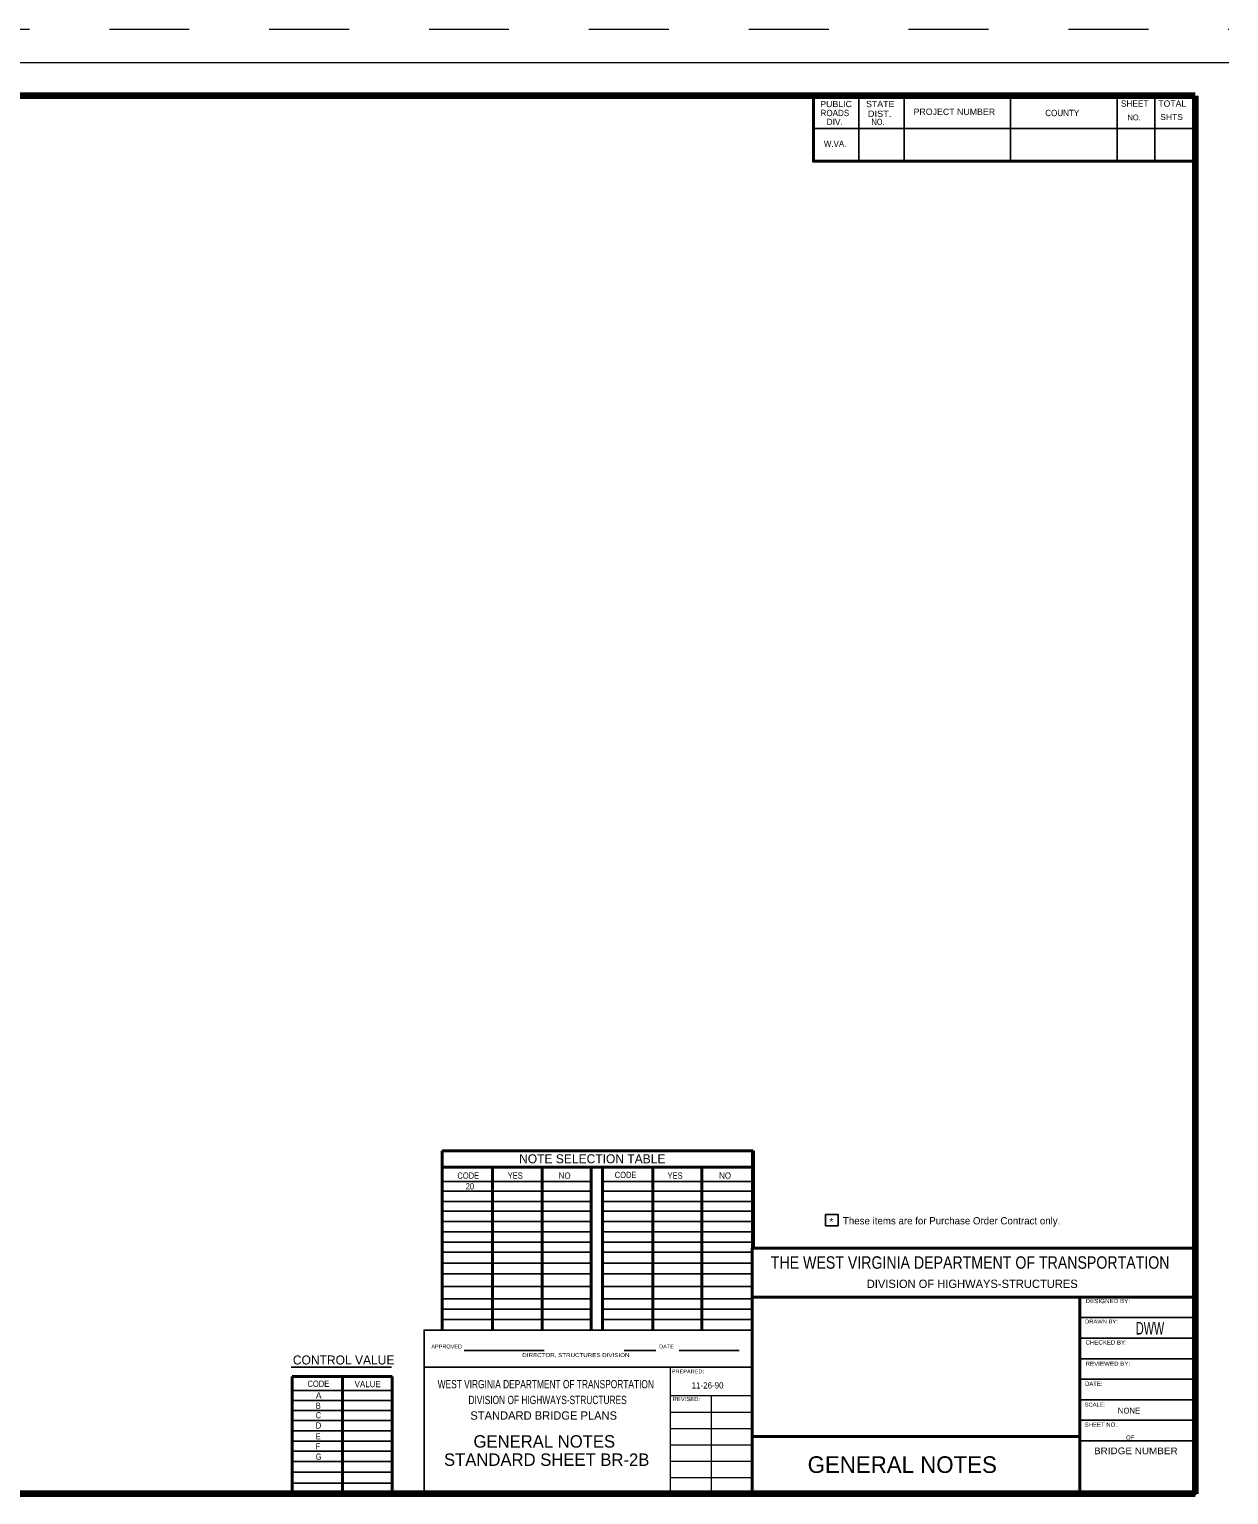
# Model space of a CAD drawing. Extents: x -2.94 to 3.45, y 0.57 to 4.
# Drawn here: x -1.435 to 0.065, y 2.169 to 4.003 of the extents above; entities that cross this region are included whole.
import ezdxf
from ezdxf.enums import TextEntityAlignment as Align

# ---------------------------------------------------------------- set-up
doc = ezdxf.new("R2010")
doc.units = 0
doc.header["$LTSCALE"] = 0.0036
doc.header["$PDMODE"] = 32
doc.header["$PDSIZE"] = 0.0018
doc.linetypes.add('DOTTED', pattern=[1.5, 0.3, -1.2])
doc.linetypes.add('LONG_DASHED', pattern=[7.5, 6, -1.5])
for name, color, linetype, lineweight in [('1', 7, 'Continuous', 13), ('3', 7, 'Continuous', 25), ('61', 7, 'Continuous', 25)]:
    doc.layers.add(name, color=color, linetype=linetype, lineweight=lineweight)

msp = doc.modelspace()

# ---------------------------------------------------------------- linework, layer by layer
at = {"layer": '1', "linetype": 'LONG_DASHED'}
msp.add_line((-2.935167, 4.002917), (0.065333, 4.002917), dxfattribs=at)
at = {"layer": '1'}
for p, q in [((-2.935167, 3.96125), (0.065333, 3.96125)), ((-0.633417, 2.328333), (-0.633417, 2.169667)), ((-0.633417, 2.292833), (-0.530833, 2.292833)), ((-0.582167, 2.29325), (-0.582167, 2.169667)), ((-0.633417, 2.27225), (-0.530833, 2.27225)), ((-0.633417, 2.251667), (-0.530833, 2.251667)), ((-0.633417, 2.231167), (-0.530833, 2.231167)), ((-0.633417, 2.21075), (-0.530833, 2.21075)), ((-0.633417, 2.190167), (-0.530833, 2.190167))]:
    msp.add_line(p, q, dxfattribs=at)
at = {"layer": '1', "lineweight": 158}
for p, q in [((0.023417, 3.919667), (-2.789083, 3.919667)), ((0.023417, 3.919667), (0.023417, 2.169667)), ((0.023417, 2.169667), (-2.789083, 2.169667))]:
    msp.add_line(p, q, dxfattribs=at)
at = {"layer": '1', "lineweight": 25}
for p, q in [((-0.3975, 3.919667), (-0.3975, 3.837667)), ((-0.340917, 3.919667), (-0.340917, 3.837667)), ((-0.2075, 3.919667), (-0.2075, 3.837667)), ((-0.07425, 3.919667), (-0.07425, 3.837667)), ((-0.026917, 3.919667), (-0.026917, 3.837667)), ((-0.454167, 3.87875), (0.023417, 3.87875)), ((-0.12075, 2.390417), (0.023417, 2.390417)), ((-0.9415, 2.37475), (-0.530833, 2.37475)), ((-0.9415, 2.37475), (-0.530833, 2.37475)), ((-0.12075, 2.3645), (0.023417, 2.3645)), ((-0.12075, 2.338667), (0.023417, 2.338667)), ((-0.9415, 2.328333), (-0.530833, 2.328333)), ((-0.12075, 2.313167), (0.023417, 2.313167)), ((-0.12075, 2.287417), (0.023417, 2.287417)), ((-0.12075, 2.262), (0.023417, 2.262)), ((-0.12075, 2.236), (0.023417, 2.236))]:
    msp.add_line(p, q, dxfattribs=at)
at = {"layer": '1', "lineweight": 40}
for p, q in [((-0.530833, 2.415833), (0.023417, 2.415833)), ((-0.12075, 2.415833), (-0.12075, 2.169667)), ((-0.530833, 2.241417), (-0.12075, 2.241417))]:
    msp.add_line(p, q, dxfattribs=at)
at = {"layer": '1', "linetype": 'DOTTED', "lineweight": 25}
for p, q in [((-0.89125, 2.349083), (-0.651583, 2.349083)), ((-0.622417, 2.349083), (-0.547083, 2.349083))]:
    msp.add_line(p, q, dxfattribs=at)
at = {"layer": '1', "lineweight": 40}
for points in [[(-0.454167, 3.919667), (-0.454167, 3.837667), (0.023417, 3.837667)], [(-0.530833, 2.169667), (-0.530833, 2.477333), (0.023417, 2.477333)]]:
    msp.add_lwpolyline(points, dxfattribs=at)
at = {"layer": '1', "lineweight": 25}
msp.add_lwpolyline([(-0.9415, 2.169667), (-0.9415, 2.37475), (-0.530833, 2.37475)], dxfattribs=at)
at = {"layer": '1'}
msp.add_point((0.023417, 2.169667), dxfattribs=at)
at = {"layer": '3'}
msp.add_lwpolyline([(-0.439083, 2.519583), (-0.439083, 2.505333), (-0.4235, 2.505333), (-0.4235, 2.519583)], close=True, dxfattribs=at)
at = {"layer": '61', "lineweight": 40}
for p, q in [((-0.918833, 2.599), (-0.918833, 2.37475)), ((-0.918833, 2.599), (-0.52975, 2.599)), ((-0.918917, 2.578583), (-0.529833, 2.578583)), ((-0.856, 2.37475), (-0.856, 2.578417)), ((-0.793833, 2.37475), (-0.793833, 2.578583)), ((-0.7325, 2.37475), (-0.7325, 2.578667)), ((-0.718, 2.37475), (-0.718, 2.5785)), ((-0.65525, 2.37475), (-0.65525, 2.5785)), ((-0.593833, 2.37475), (-0.593833, 2.578583)), ((-0.918833, 2.5245), (-0.918833, 2.511333)), ((-1.1065, 2.31675), (-0.981417, 2.31675)), ((-1.106417, 2.316833), (-1.106417, 2.17025)), ((-1.043583, 2.170167), (-1.043583, 2.3165)), ((-0.981417, 2.17025), (-0.981417, 2.31675)), ((-1.106417, 2.262583), (-1.106417, 2.2495)), ((-1.106417, 2.170167), (-0.981417, 2.170167))]:
    msp.add_line(p, q, dxfattribs=at)
at = {"layer": '61', "lineweight": 53}
msp.add_line((-0.529833, 2.477333), (-0.529833, 2.599), dxfattribs=at)
at = {"layer": '61'}
for p, q in [((-0.7325, 2.560917), (-0.919, 2.560917)), ((-0.529833, 2.560917), (-0.718083, 2.560917)), ((-0.7325, 2.5485), (-0.918917, 2.5485)), ((-0.732417, 2.535917), (-0.918833, 2.535917)), ((-0.529833, 2.5485), (-0.718083, 2.5485)), ((-0.529833, 2.535917), (-0.718083, 2.535917)), ((-0.732417, 2.5235), (-0.918833, 2.5235)), ((-0.918833, 2.522833), (-0.918833, 2.50725)), ((-0.529833, 2.5235), (-0.718083, 2.5235)), ((-0.918917, 2.5105), (-0.732417, 2.5105)), ((-0.918917, 2.49775), (-0.7325, 2.49775)), ((-0.918833, 2.498167), (-0.918833, 2.485)), ((-0.718083, 2.5105), (-0.530833, 2.5105)), ((-0.718083, 2.49775), (-0.530833, 2.49775)), ((-0.918833, 2.485417), (-0.918833, 2.447167)), ((-0.918833, 2.485), (-0.7325, 2.485)), ((-0.718083, 2.485), (-0.531667, 2.485)), ((-0.918833, 2.47225), (-0.732417, 2.47225)), ((-0.918833, 2.471833), (-0.918833, 2.458667)), ((-0.918833, 2.458667), (-0.732417, 2.458667)), ((-0.718083, 2.47225), (-0.53, 2.47225)), ((-0.718, 2.458667), (-0.530833, 2.458667)), ((-0.918833, 2.445167), (-0.732417, 2.445167)), ((-0.718083, 2.445167), (-0.530833, 2.445167)), ((-0.918833, 2.4295), (-0.732417, 2.4295)), ((-0.718083, 2.4295), (-0.530833, 2.4295)), ((-0.918833, 2.413917), (-0.732417, 2.413917)), ((-0.718083, 2.413917), (-0.530833, 2.413917)), ((-0.918833, 2.400917), (-0.732417, 2.400917)), ((-0.918833, 2.387917), (-0.732417, 2.387917)), ((-0.718083, 2.400917), (-0.530833, 2.400917)), ((-0.718083, 2.387917), (-0.530833, 2.387917)), ((-1.107917, 2.328417), (-0.982167, 2.328417)), ((-0.981417, 2.299), (-1.106583, 2.299)), ((-0.981417, 2.286583), (-1.1065, 2.286583)), ((-0.981417, 2.274), (-1.106417, 2.274)), ((-0.981417, 2.261583), (-1.106417, 2.261583)), ((-1.106417, 2.261), (-1.106417, 2.245333)), ((-1.1065, 2.248667), (-0.981417, 2.248667)), ((-1.1065, 2.235917), (-0.981417, 2.235917)), ((-1.106417, 2.23625), (-1.106417, 2.223167)), ((-1.106417, 2.2235), (-1.106417, 2.18525)), ((-1.106417, 2.223167), (-0.981417, 2.223167)), ((-1.106417, 2.210417), (-0.981417, 2.210417)), ((-1.106417, 2.21), (-1.106417, 2.196833)), ((-1.106417, 2.196833), (-0.981417, 2.196833)), ((-1.106417, 2.1965), (-1.106417, 2.17025)), ((-1.106417, 2.183333), (-0.981417, 2.183333))]:
    msp.add_line(p, q, dxfattribs=at)

# ---------------------------------------------------------------- texts
at = {"layer": '1'}
for s, height, width, p in [('PUBLIC', 0.007834, 1.05, (-0.425917, 3.9055)), ('STATE', 0.007834, 1.05, (-0.370667, 3.9055)), ('TOTAL', 0.007751, 1.05, (-0.00525, 3.906083)), ('ROADS', 0.007918, 0.95, (-0.427375, 3.89425)), ('DIST.', 0.007834, 1.1, (-0.371458, 3.893333)), ('NO.', 0.007834, 0.85, (-0.373417, 3.883083)), ('PROJECT NUMBER', 0.007834, 1.05, (-0.277917, 3.895833)), ('COUNTY', 0.007918, 0.95, (-0.142917, 3.89425)), ('NO.', 0.007334, 0.95, (-0.053, 3.888917)), ('SHTS', 0.007251, 1.1, (-0.006167, 3.8895)), ('W.VA.', 0.007834, 0.95, (-0.427083, 3.85575)), ('THE WEST VIRGINIA DEPARTMENT OF TRANSPORTATION', 0.01558, 0.85, (-0.258167, 2.451583)), ('WEST VIRGINIA DEPARTMENT OF TRANSPORTATION', 0.01042, 0.75, (-0.789125, 2.301917)), ('DIVISION OF HIGHWAYS-STRUCTURES', 0.01042, 0.75, (-0.786875, 2.282167)), ('BRIDGE NUMBER', 0.008416, 1.1, (-0.050875, 2.219417))]:
    msp.add_text(s, height=height, dxfattribs=dict(at, width=width)).set_placement(p, align=Align.CENTER)
for s, height, p in [('SHEET', 0.007751, (-0.052208, 3.906083)), ('DIV.', 0.007834, (-0.427625, 3.883083)), ('DIVISION OF HIGHWAYS-STRUCTURES ', 0.01042, (-0.253625, 2.4275))]:
    msp.add_text(s, height=height, dxfattribs=at).set_placement(p, align=Align.CENTER)
for s, height, width, p in [('DESIGNED BY:', 0.005335, 1.1, (-0.113833, 2.4085)), ('DRAWN BY:', 0.004918, 1.1, (-0.114333, 2.383083)), ('DWW', 0.01558, 0.65, (-0.05075, 2.36925)), ('APPROVED', 0.004917, 1.05, (-0.932333, 2.35175)), ('DATE', 0.004917, 1.05, (-0.64725, 2.35175)), ('CHECKED BY:', 0.005419, 1.05, (-0.113833, 2.356667)), ('DIRECTOR, STRUCTURES DIVISION', 0.004835, 1.2, (-0.8185, 2.341083)), ('REVIEWED BY:', 0.004835, 1.2, (-0.113833, 2.330333)), ('PREPARED:', 0.004751, 1.1, (-0.6315, 2.320667)), ('SCALE:', 0.004918, 1.1, (-0.114833, 2.279)), ('SHEET NO.:', 0.005335, 1.05, (-0.114833, 2.25375)), ('OF', 0.005419, 0.85, (-0.063, 2.237583))]:
    msp.add_text(s, height=height, dxfattribs=dict(at, width=width)).set_placement(p)
for s, height, p in [('DATE:', 0.005335, (-0.114333, 2.305)), ('REVISED:', 0.005335, (-0.6305, 2.285833)), ('NONE', 0.007251, (-0.073333, 2.270333))]:
    msp.add_text(s, height=height, dxfattribs=at).set_placement(p)
at = {"layer": '3'}
for s, height, p in [('*', 0.009083, (-0.43425, 2.505833)), ('These items are for Purchase Order Contract only.', 0.009083, (-0.417333, 2.507083)), ('STANDARD BRIDGE PLANS', 0.01042, (-0.8835, 2.262667)), ('GENERAL NOTES', 0.01558, (-0.879583, 2.227667)), ('STANDARD SHEET BR-2B', 0.01558, (-0.9165, 2.204833)), ('GENERAL NOTES', 0.02083, (-0.4615, 2.196))]:
    msp.add_text(s, height=height, dxfattribs=at).set_placement(p)
at = {"layer": '61'}
for s, p in [('NOTE SELECTION TABLE', (-0.8225, 2.583583)), ('CONTROL VALUE', (-1.105583, 2.33175))]:
    msp.add_text(s, height=0.01125, dxfattribs=at).set_placement(p)
for s, height, width, p in [('CODE', 0.007833, 0.9, (-0.89975, 2.56425)), ('YES', 0.007833, 0.9, (-0.83675, 2.56425)), ('NO', 0.007833, 0.95, (-0.773, 2.56425)), ('CODE', 0.007833, 0.9, (-0.702917, 2.565083)), ('YES', 0.007833, 0.9, (-0.63675, 2.56425)), ('NO', 0.007833, 0.95, (-0.57225, 2.56425)), ('20', 0.007833, 0.9, (-0.889333, 2.550833)), ('CODE', 0.007833, 0.9, (-1.087333, 2.30375)), ('VALUE', 0.007833, 0.95, (-1.028333, 2.303333)), ('A', 0.00775, 1.05, (-1.076917, 2.289)), ('11-26-90', 0.007833, 0.95, (-0.606583, 2.301667)), ('B', 0.00775, 0.85, (-1.076917, 2.27625)), ('C', 0.007833, 0.8, (-1.076917, 2.26425)), ('D', 0.007833, 0.9, (-1.076917, 2.2515)), ('E', 0.00775, 0.8, (-1.076917, 2.238)), ('G', 0.00775, 0.85, (-1.076917, 2.2125)), ('F', 0.00775, 0.8, (-1.076917, 2.22525))]:
    msp.add_text(s, height=height, dxfattribs=dict(at, width=width)).set_placement(p)

doc.saveas('drawing.dxf')
